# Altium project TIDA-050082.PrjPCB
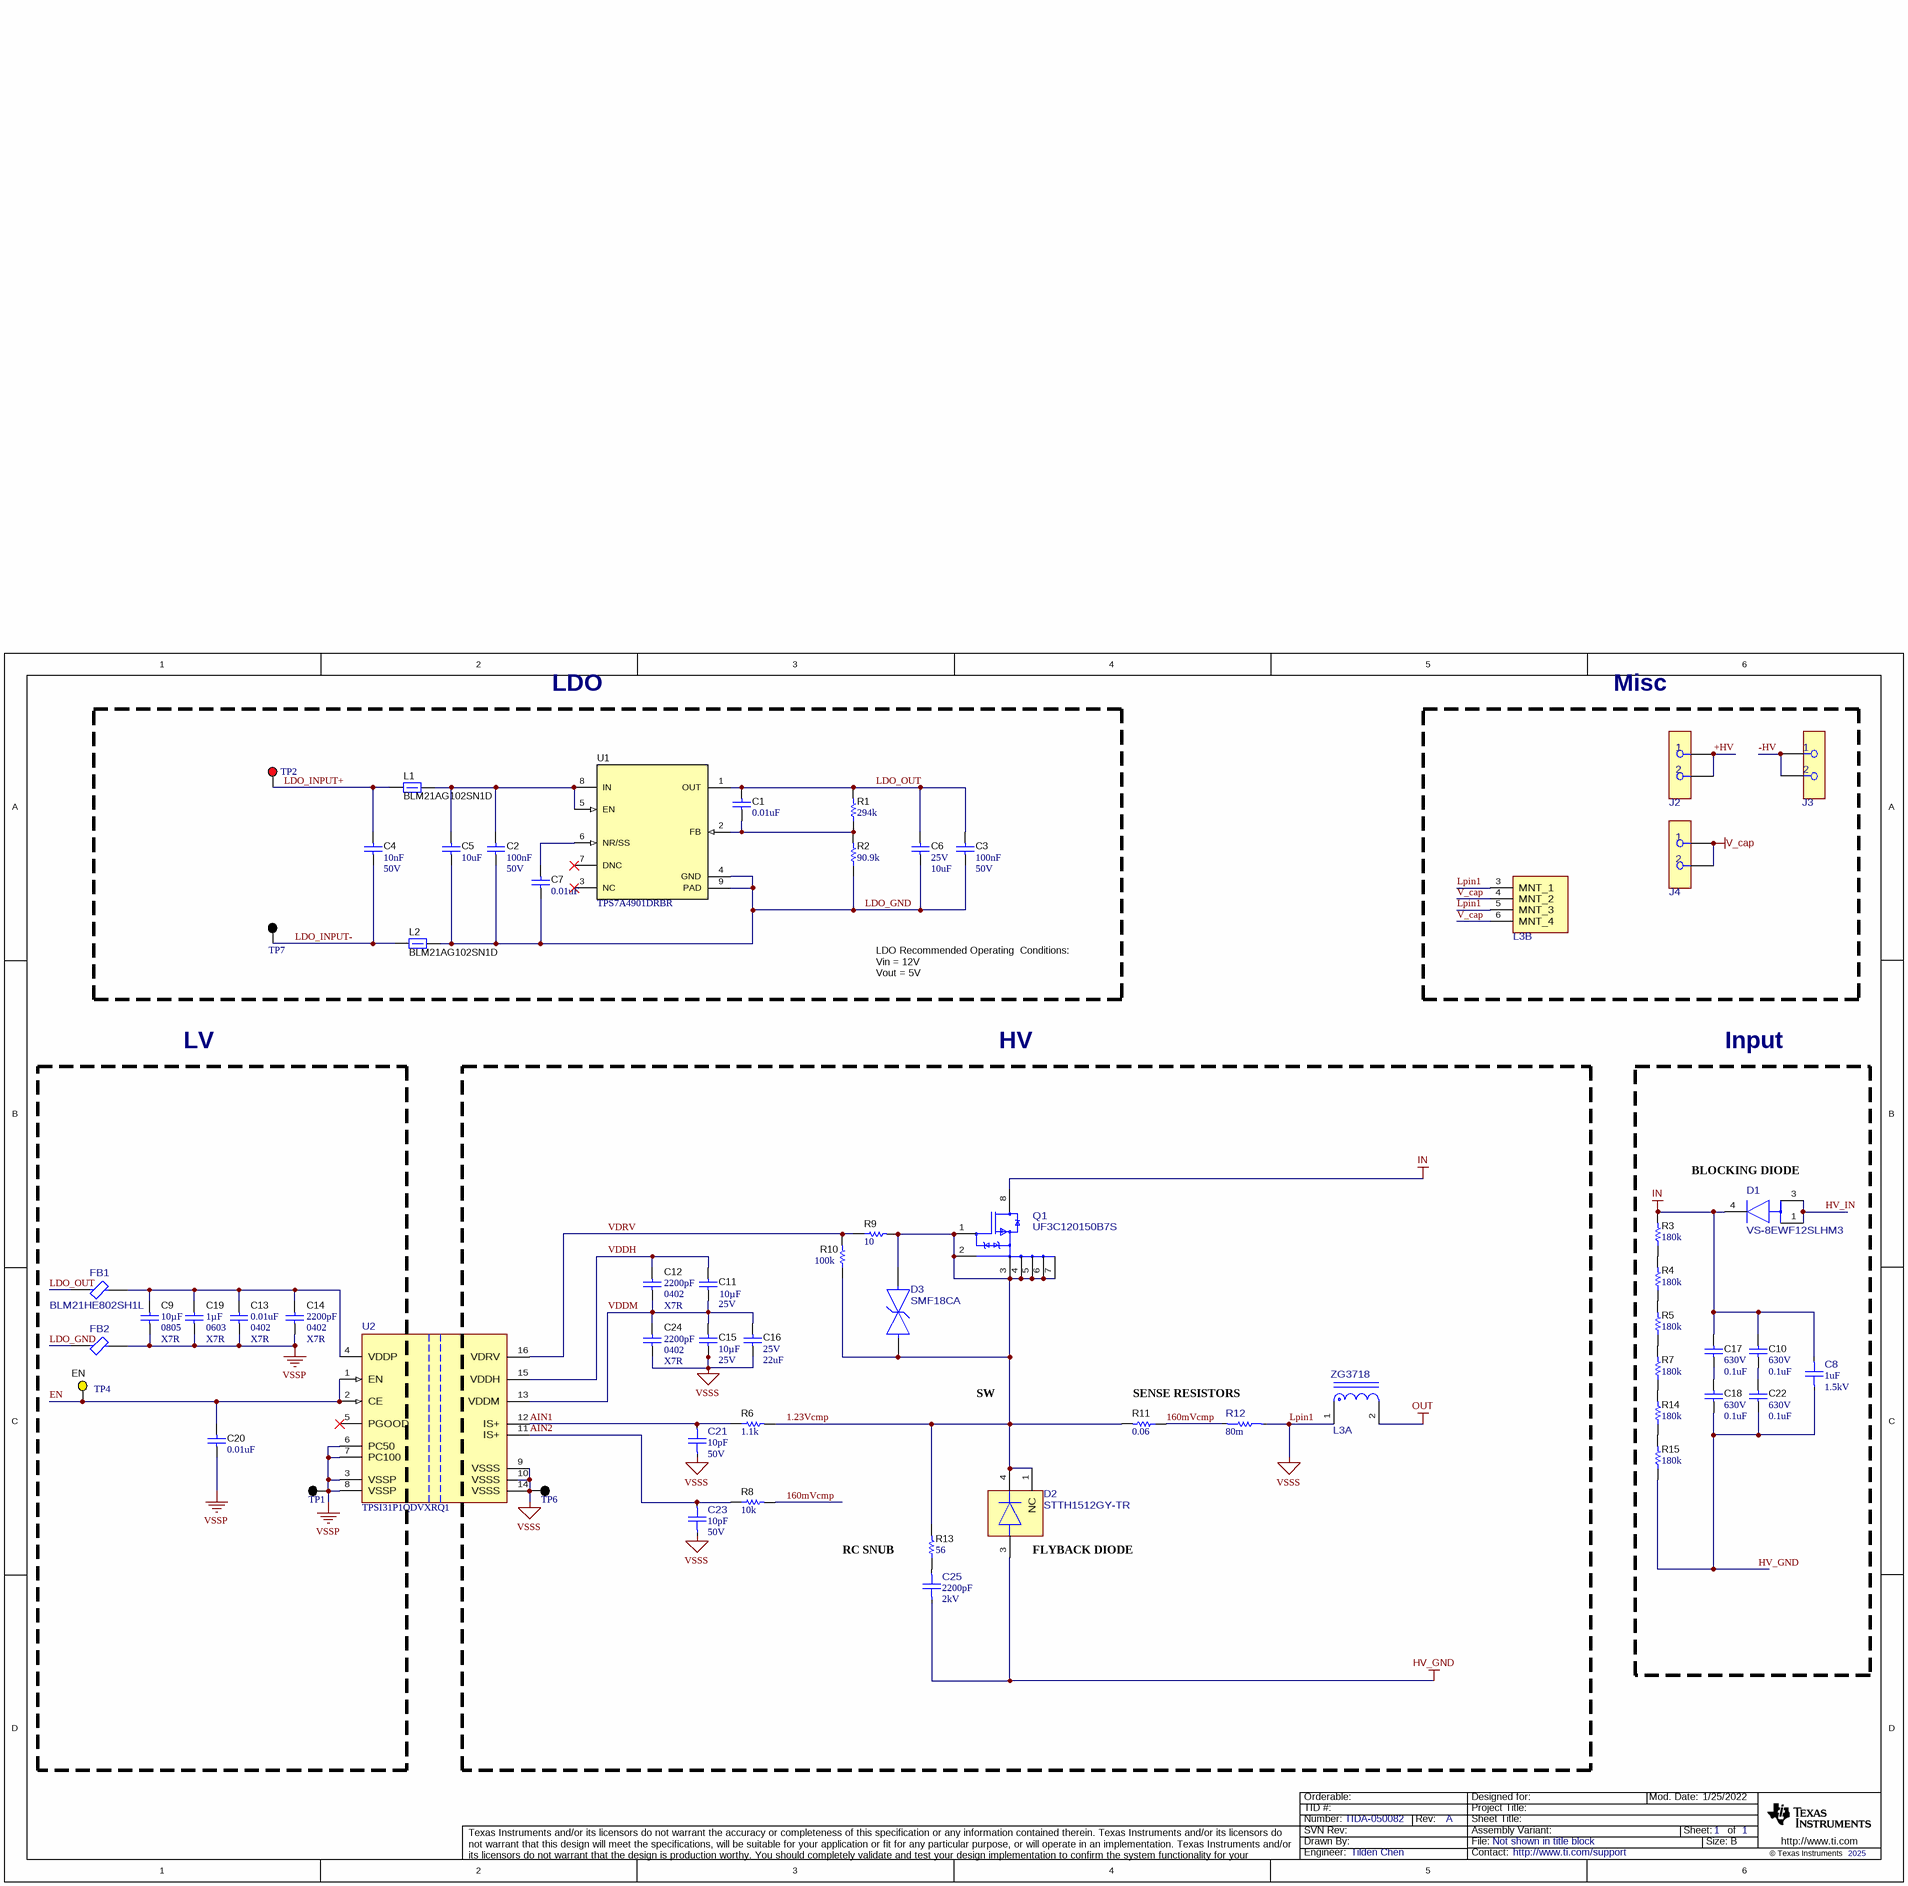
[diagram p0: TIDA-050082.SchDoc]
CopyrightYear: 2025; PCB_Rev: A; PRJ_Engineer: Tilden Chen; PRJ_Number: TIDA-050082; SCH_Rev: A; TechSupport: http://www.ti.com/support
2 sheets, 66 parts. Net scope: global (net labels, ports and power ports of the same name join across sheets).
Board file: TIDA-050082.PcbDoc
Sheets:
  TIDA-050082.SchDoc
  TIDA-050082-Hardware.SchDoc

## Sheet TIDA-050082.SchDoc
size 431 x 279 mm; Date: Not shown in title block; ApprovedBy: Not shown in title block; CheckedBy: Not shown in title block; Author: Not shown in title block; CompanyName: Not shown in title block; Engineer: Not shown in title block; Organization: Not shown in title block; Address1: Not shown in title block; Address2: Not shown in title block; Address3: Not shown in title block; Address4: Not shown in title block; DocumentNumber: 1; Revision: Use project parameter SCH_Rev; SheetNumber: 1; SheetTotal: 1; PageSetup: Record=PageOptions¦CenterHorizontal=True¦CenterVertical=True¦PrintScale=1.00¦XCorrection=1.00¦YCorrection=1.00¦PrintKind=0¦BorderSize=5000000¦LeftOffset=0¦BottomOffset=0¦Orientation=2¦PaperLength=1000¦PaperWidth=1000¦Scale=100¦PaperSource=15¦PrintQuality=600¦MediaType=1¦DitherType=10¦PaperKind=Letter¦PrintScaleMode=1

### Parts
C1  ValueDisplayed: 0.01uF  [0402]  (hidden comment: GRM155R71E103KA01D)
C2  Cap_F: 100nF  VDC_V: 50V  [0603]  (hidden comment: CGA3E2X7R1H104K080AA)
C3  Cap_F: 100nF  VDC_V: 50V  [0603]  (hidden comment: CGA3E2X7R1H104K080AA)
C4  Cap_F: 10nF  VDC_V: 50V  [0603]  (hidden comment: GCM188R71H103KA37D)
C5  ValueDisplayed: 10uF  [0603]  (hidden comment: GRT188R61E106ME13D)
C6  VDC_V: 25V  ValueDisplayed: 10uF  [1206_180]  (hidden comment: GRM31CR71E106KA12L)
C7  ValueDisplayed: 0.01uF  [0402]  (hidden comment: GRM155R71E103KA01D)
C8  ValueDisplayed: 1uF  VDC_V: 1.5kV  [FP-C4AQSBU4100A1WJ_RADIAL-MFG]  (hidden comment: C4AQSBU4100A1WJ)
C9  TempCo: X7R  Cap_Case: 0805  Cap_F: 10µF  [0805_HV]  (hidden comment: GRM21BZ71E106KE15L)
C10  VDC_V: 630V  ValueDisplayed: 0.1uF  [1210_280]  (hidden comment: C1210C104KBRAC7800)
C11  Cap_F: 10µF  VDC_V: 25V  [0805_HV]  (hidden comment: GRM21BZ71E106KE15L)
C12  TempCo: X7R  ValueDisplayed: 2200pF  [0402]  (hidden comment: 885012205027)
C13  TempCo: X7R  ValueDisplayed: 0.01uF  [0402]  (hidden comment: GRM155R71E103KA01D)
C14  TempCo: X7R  ValueDisplayed: 2200pF  [0402]  (hidden comment: 885012205027)
C15  Cap_F: 10µF  VDC_V: 25V  [0805_HV]  (hidden comment: GRM21BZ71E106KE15L)
C16  VDC_V: 25V  ValueDisplayed: 22uF  [0805_HV]  (hidden comment: GRM21BR61E226ME44L)
C17  VDC_V: 630V  ValueDisplayed: 0.1uF  [1210_280]  (hidden comment: C1210C104KBRAC7800)
C18  VDC_V: 630V  ValueDisplayed: 0.1uF  [1210_280]  (hidden comment: C1210C104KBRAC7800)
C19  TempCo: X7R  Cap_F: 1µF  [0603]  (hidden comment: CGA3E1X7R1C105K080AC)
C20  ValueDisplayed: 0.01uF  [0402]  (hidden comment: GRM155R71E103KA01D)
C21  ValueDisplayed: 10pF  VDC_V: 50V  [FP-C0402C100K5RAC7867_0402-MFG]  (hidden comment: C0402C100K5RAC7867)
C22  VDC_V: 630V  ValueDisplayed: 0.1uF  [1210_280]  (hidden comment: C1210C104KBRAC7800)
C23  ValueDisplayed: 10pF  VDC_V: 50V  [FP-C0402C100K5RAC7867_0402-MFG]  (hidden comment: C0402C100K5RAC7867)
C24  TempCo: X7R  ValueDisplayed: 2200pF  [0402]  (hidden comment: 885012205027)
C25  ValueDisplayed: 2200pF  VDC_V: 2kV  [FP-C1206X222KGRACAUTO_1206-MFG]  (hidden comment: C1206X222KGRACAUTO)
D1  VS-8EWF12SLHM3  [FP-VS-8EWF12SLHM3_DPAK-MFG]
D2  STTH1512GY-TR  [FP-STTH1512GY-TR_D2PAK-MFG]
D3  SMF18CA  [FP-SMF18CA_SOD-123FL-MFG]
FB1  BLM21HE802SH1L  [FP-BLM21HE802SH1L_0805-MFG]
FB2  BLM21HE802SH1L  [FP-BLM21HE802SH1L_0805-MFG]  (value not drawn)
J2  691250610002  [FP-691250610002_CONN_TERM_BLOCK2-MFG]  (value not drawn)
J3  691250610002  [FP-691250610002_CONN_TERM_BLOCK2-MFG]  (value not drawn)
J4  691250610002  [FP-691250610002_CONN_TERM_BLOCK2-MFG]  (value not drawn)
L1  BLM21AG102SN1D  [0805_HV]
L2  BLM21AG102SN1D  [0805_HV]
L3  ZG3718  [FP-ZG3718_PTH6-MFG]  (parts A,B of 2)
Q1  UF3C120150B7S  [FP-UF3C120150B7S_D2PAK7-MFG]
R1  ValueDisplayed: 294k  [0402]  (hidden comment: ERJ-2RKF2943X)
R2  ValueDisplayed: 90.9k  [0402]  (hidden comment: ERJ-2RKF9092X)
R3  ValueDisplayed: 180k  [1206]  (hidden comment: CRCW1206180KJNEA)
R4  ValueDisplayed: 180k  [1206]  (hidden comment: CRCW1206180KJNEA)
R5  ValueDisplayed: 180k  [1206]  (hidden comment: CRCW1206180KJNEA)
R6  ValueDisplayed: 1.1k  [0402]  (hidden comment: CRCW04021K10JNED)
R7  ValueDisplayed: 180k  [1206]  (hidden comment: CRCW1206180KJNEA)
R8  ValueDisplayed: 10k  [0402]  (hidden comment: ERJ-2GEJ103X)
R9  ValueDisplayed: 10  [0603]  (hidden comment: CRCW060310R0JNEA)
R10  ValueDisplayed: 100k  [0603]  (hidden comment: ERJ-3GEYJ104V)
R11  ValueDisplayed: 0.06  [2512]  (hidden comment: WSL2512R0600FEA)
R12  value 80m  [FP-TLRP3A20CR080FTE_2512-MFG]  (hidden comment: TLRP3A20CR080FTE)
R13  ValueDisplayed: 56  [1206]  (hidden comment: CRCW120656R0JNEA)
R14  ValueDisplayed: 180k  [1206]  (hidden comment: CRCW1206180KJNEA)
R15  ValueDisplayed: 180k  [1206]  (hidden comment: CRCW1206180KJNEA)
TP1  5011  [Keystone5011]  (value not drawn)
TP2  (no value)  [Keystone5010]
TP4  EN  [Keystone5014]
TP6  5011  [Keystone5011]  (value not drawn)
TP7  5011  [Keystone5011]  (value not drawn)
U1  TPS7A4901DRBR  [DRB0008A]
U2  TPSI31P1QDVXRQ1  [DVX0016A-MFG]

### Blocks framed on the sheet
LDO: C1-C7 L1 L2 R1 R2 TP2 TP7 U1
Misc: J2-J4 L3
LV: C9 C13 C14 C19 C20 FB1 FB2 TP1 TP4
HV: C11 C12 C15 C16 C21 C23-C25 D2 D3 L3 Q1 R6 R8-R13 TP6
Input: C8 C10 C17 C18 C22 D1 R3-R5 R7 R14 R15

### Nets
HV_GND: C8.1 C18.2 C22.2 C25.1 D2.3(A) R15.1
IN: C8.2 C10.1 C17.1 D1.4(Cathode) Q1.8(D) R3.2
Lpin1: C15.2 C16.2 C21.1 C23.1 C24.2 L3.1 L3.3(MNT_1) L3.5(MNT_3) R12.1 TP6.1 U2.9(VSSS) U2.10(VSSS) U2.14(VSSS)  [also labelled VSSS]
OUT: L3.2
V_cap: J4.1 J4.2 L3.4(MNT_2) L3.6(MNT_4)
VSSP: C9.2 C13.2 C14.2 C19.2 C20.2 FB2.2 TP1.1 U2.3(VSSP) U2.6(PC50) U2.7(PC100) U2.8(VSSP)
1.23Vcmp: D2.1(NC) D2.4(K) D3.1 D3.2 Q1.1(G) Q1.2(KS) Q1.3(S) Q1.4(S) Q1.5(S) Q1.6(S) Q1.7(S) R6.2 R9.2 R10.1 R11.2 R13.2
160mVcmp: R8.2 R11.1 R12.2
+HV: J2.1 J2.2
-HV: J3.1 J3.2
AIN1: C21.2 R6.1 U2.12(IS+)
AIN2: C23.2 R8.1 U2.11(IS+)
EN: C20.1 TP4.1 U2.1(EN) U2.2(CE)
HV_IN: D1.1(Anode) D1.3(Anode)
LDO_GND: C2.2 C3.2 C5.2 C6.2 C7.2 FB2.1 L2.2 R2.1 U1.4(GND) U1.9(PAD)
LDO_INPUT+: C4.1 L1.1 TP2.1
LDO_INPUT-: C4.2 L2.1 TP7.1
LDO_OUT: C1.1 C3.1 C6.1 FB1.1 R1.2 U1.1(OUT)
VDDH: C11.1 C12.1 U2.15(VDDH)
VDDM: C11.2 C12.2 C15.1 C16.1 C24.1 U2.13(VDDM)
VDRV: R9.1 R10.2 U2.16(VDRV)
NetC1_2: C1.2 R1.1 R2.2 U1.2(FB)
NetC2_1: C2.1 C5.1 L1.2 U1.5(EN) U1.8(IN)
NetC7_1: C7.1 U1.6(NR/SS)
NetC9_1: C9.1 C13.1 C14.1 C19.1 FB1.2 U2.4(VDDP)
NetC10_2: C10.2 C22.1
NetC17_2: C17.2 C18.1
NetC25_2: C25.2 R13.1
NetR3_1: R3.1 R4.2
NetR4_1: R4.1 R5.2
NetR5_1: R5.1 R7.2
NetR7_1: R7.1 R14.2
NetR14_1: R14.1 R15.2

Not connected (* = marked no-connect by the designer): U1 3(NC)* 7(DNC)*; U2 5(PGOOD)*

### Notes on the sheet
- LDO Recommended Operating  Conditions:
  Vin = 12V
  Vout = 5V
- (near D1) BLOCKING DIODE
- SW
- SENSE RESISTORS
- RC SNUB
- (near D2) FLYBACK DIODE

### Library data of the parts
C1 C7 C13 C20 = CMP-0006658-2: CAP, CERM, 0.01 uF, 25 V, +/- 10%, X7R, 0402; Manufacturer: MuRata; TaMin_C: -55°C; Polarized: N; SizeAreaWB_mm2: 3; Value1: Unknown; U/M: EA; Value: 0.01uF; TaMax_C: 125°C; SizeZ_mm: 0.6; SizeX_mm: 1; SizeY_mm: 0.5; Value2: 25V; Cap_F: 10nF; AEC Category: Q200
C2 C3 = CMP-0007078-4: CAP, CERM, 0.1 uF, 50 V, +/- 10%, X7R, AEC-Q200 Grade 1, 0603; Manufacturer: TDK; TaMin_C: -55°C; ESR_ohm: 29.6m; Polarized: N; SizeAreaWB_mm2: 4.68; Value1: 0.0296 ohm; U/M: EA; Value: 0.1uF; TaMax_C: 125°C; SizeZ_mm: 1; SizeX_mm: 1.6; SizeY_mm: 0.8; SizeArea_mm2: 1.28; AEC Qualified: Y; IRMS_A: 971.99mA; AEC Category: Q200
C4 = CMP-0007143-4: CAP, CERM, 0.01 uF, 50 V, +/- 10%, X7R, AEC-Q200 Grade 1, 0603; Manufacturer: MuRata; TaMin_C: -55°C; Polarized: N; SizeAreaWB_mm2: 4.68; Value1: Unknown; U/M: EA; Value: 0.01uF; TaMax_C: 125°C; SizeZ_mm: 1; SizeX_mm: 1.6; SizeY_mm: 0.8; SizeArea_mm2: 1.28; AEC Qualified: Y; AEC Category: Q200
C5 = CMP-0007501-5: CAP, CERM, 10 uF, 25 V, +/- 20%, X5R, 0603; Manufacturer: MuRata; TaMin_C: -55°C; Polarized: N; SizeAreaWB_mm2: 4.68; Value1: Unknown; U/M: EA; Value: 10uF; TaMax_C: 85°C; SizeZ_mm: 1; SizeX_mm: 1.6; SizeY_mm: 0.8; Value2: 25V; SizeArea_mm2: 1.28; Cap_F: 10µF; AEC Category: Q200
C6 = CMP-0008965-2: CAP, CERM, 10 uF, 25 V, +/- 10%, X7R, 1206; Manufacturer: MuRata; TaMin_C: -55°C; Polarized: N; SizeAreaWB_mm2: 10.92; Value1: Unknown; U/M: EA; Value: 10uF; TaMax_C: 125°C; SizeZ_mm: 1.8; SizeX_mm: 3.2; SizeY_mm: 1.6; Cap_Case: 2220; SizeArea_mm2: 5.12; Cap_F: 10µF; AEC Category: Q200
C8 = CMP-0122633-1: 1 µF Film Capacitor 1500V (1.5kV) Polypropylene (PP), Metallized Radial; Manufacturer: KEMET; AEC Grade: Grade 2; AEC Qualified: Yes; Cap_F: 1µF; SizeZ_mm: 20.2mm; Tolerance_%: 5%; Value: 1µF
C9 = CMP-0008378-2: CAP, CERM, 10 uF, 25 V, +/- 10%, X7R, 0805; Manufacturer: MuRata; TaMin_C: -55°C; Polarized: N; SizeAreaWB_mm2: 6.75; Value1: Unknown; U/M: EA; Value: 10uF; TaMax_C: 125°C; SizeZ_mm: 1.45; SizeX_mm: 2; SizeY_mm: 1.25; Value2: 25V; SizeArea_mm2: 2.5; AEC Category: Q200
C10 C17 C18 C22 = CMP-0009076-1: CAP, CERM, 0.1 uF, 630 V, +/- 10%, X7R, 1210; Manufacturer: Kemet; TaMin_C: -55°C; Polarized: N; SizeAreaWB_mm2: 14.7; Value1: Unknown; U/M: EA; Value: 0.1uF; TaMax_C: 125°C; SizeZ_mm: 2.8; SizeX_mm: 3.2; SizeY_mm: 2.5; Cap_Case: 1210; SizeArea_mm2: 8; Cap_F: 100nF; AEC Category: Q200
C11 C15 = CMP-0008378-2: CAP, CERM, 10 uF, 25 V, +/- 10%, X7R, 0805; Manufacturer: MuRata; TaMin_C: -55°C; Polarized: N; SizeAreaWB_mm2: 6.75; Value1: Unknown; U/M: EA; Value: 10uF; TaMax_C: 125°C; SizeZ_mm: 1.45; SizeX_mm: 2; SizeY_mm: 1.25; Cap_Case: 0805; SizeArea_mm2: 2.5; AEC Category: Q200
C12 C14 C24 = CMP-0006225-2: CAP, CERM, 2200 pF, 16 V, +/- 10%, X7R, 0402; Manufacturer: Wurth Elektronik; TaMin_C: -55°C; Polarized: N; SizeAreaWB_mm2: 3; Value1: Unknown; U/M: EA; Value: 2200pF; TaMax_C: 125°C; SizeZ_mm: 0.6; SizeX_mm: 1; SizeY_mm: 0.5; Value2: 16V; Cap_F: 2.2nF; AEC Category: Q200
C16 = CMP-0008305-2: CAP, CERM, 22 uF, 25 V, +/- 20%, X5R, 0805; Manufacturer: MuRata; TaMin_C: -55°C; Polarized: N; SizeAreaWB_mm2: 6.75; Value1: Unknown; U/M: EA; Value: 22uF; TaMax_C: 85°C; SizeZ_mm: 1.45; SizeX_mm: 2; SizeY_mm: 1.25; Cap_Case: 0805; SizeArea_mm2: 2.5; Cap_F: 22µF; AEC Category: Q200
C19 = CMP-0079607-1: CAP, CERM, 1 µF, 16 V,+/- 10%, X7R, AEC-Q200 Grade 1, 0603; Manufacturer: TDK; TaMin_C: -55°C; Polarized: N; SizeAreaWB_mm2: 4.68; U/M: EA; Value: 1uF; TaMax_C: 125°C; SizeZ_mm: 1; SizeX_mm: 1.6; SizeY_mm: 0.8; Value2: 16V; SizeArea_mm2: 1.28; AEC Qualified: Y; AEC Category: Q200
C21 C23 = CMP-0122034-1: 10 pF ±10% 50V Ceramic Capacitor X7R 0402 (1005 Metric); Manufacturer: KEMET; AEC Qualified: No; SizeZ_mm: 0.55mm; TempCo: 15%; Value: 10pF
C25 = CMP-0124208-1: 2200 pF ±10% 2000V (2kV) Ceramic Capacitor X7R 1206 (3216 Metric); Manufacturer: KEMET; AEC Grade: Grade 1; AEC Qualified: Yes; Cap_F: 2.2nF; SizeZ_mm: 1.85mm; TempCo: 15%; Value: 2.2nF
D1 = CMP-0127376-1: Diode 1200 V 8A Surface Mount TO-252AA (DPAK); Manufacturer: Vishay; AEC Qualified: No; SizeZ_mm: 2.52mm; TJmax_C: 150°C; Vf_V: 1.2kV; Max Surge Forward Current: 150A; Peak Reverse Current: 0.1mA
D2 = CMP-0123451-1: Rectifier Diode Switching 1.2KV 15A 75ns Automotive 3-Pin(2+Tab) D2PAK T/R; Manufacturer: STMicroelectronics; AEC Qualified: Yes; SizeZ_mm: 4.85mm; TJmax_C: 175°C; AEC Grade: Grade 0; Max Surge Forward Current: 200A; Peak Reverse Current: 15uA; Standoff Height: 0mm
D3 = CMP-0127967-1: Diode TVS Single Bi-Dir 18V 200W 2-Pin SOD-123FL T/R; Manufacturer: Littelfuse; AEC Qualified: No; SizeZ_mm: 1.1mm; Ipp: 6.8A; Breakdown Voltage: 20V; Clamping Voltage: 29.2V; Direction: Bidirectional; Number Of Channels: 1; Standoff Height: 0mm; TJmax_C: +150°C
FB1 FB2 = CMP-0126464-1: 8 kOhms @ 100 MHz 1 Signal Line Ferrite Bead 0805 (2012 Metric) 650mA 700mOhm; Manufacturer: Murata; DCR_ohm: 0.7; SizeZ_mm: 1.45mm; AEC Grade: Grade 1; AEC Qualified: Yes; Impedance At Frequency: 8000Ω @ 100MHz; Test Frequency: 100MHz; Tolerance_%: 25%
J2-J4 = CMP-0093233-2: 2 Position Wire to Board Terminal Block Horizontal with Board 0.250" (6.35mm) Through Hole; Manufacturer: Wurth Electronics; SizeZ_mm: 21.6mm; Min Wire Gauge: 30; Is Female: yes; Row_Count: 1; Voltage_V: 450V; AEC Qualified: No; Max Wire Gauge: 10; Conn Gender: Female; Current_A: 32A; ContactFinish: Zinc
L1 L2 = CMP-0003356-1: Ferrite Bead, 1000 ohm @ 100 MHz, 0.5 A, 0805; Manufacturer: MuRata; ZTyp@100MHz_Ohm: 1k; SizeAreaWB_mm2: 6.75; DCR_ohm: 0.28; Value1: 0.28 ohm; Imax_A: 500mA; SizeZ_mm: 1.45; SizeX_mm: 2; SizeY_mm: 1.25; Value2: 0.5A; SizeArea_mm2: 2.5
L3 = CMP-0127410-1: Power inductor, 100uH-9.6A, Flat wire, TH, PQ26; Manufacturer: Coilcraft; AEC Qualified: No; DCR_ohm: 25m; Ind_H: 100µH; SizeZ_mm: 21.5mm; Value: 100uH; Test Frequency: 100kHz; Tolerance_%: 10%
Q1 = CMP-0096955-1: N-Channel 1200 V 17A (Tc) 136W (Tc) Surface Mount D2PAK-7; Manufacturer: UnitedSiC; Turn On Delay Time: 32ns; Typ Forward Diode Voltage: 1.46V; Pulse Drain Current: 38A; Reverse Recovery Time: 24ns; SizeZ_mm: 4.81mm; VdsMax_V: 2V; Reverse Recovery Charge: 67nC; AEC Qualified: No; Number Of Channels: 1; Input Capacitace At Vds: 738pF @ 100V; Standoff Height: 0mm; Threshold Vgs Max: 5.5V; Drain To Source Breakdown Voltage: 1200V; QgTyp_nC: 25.7nC @ 12V; Rdson45_ohm: 0.15; ChMode: False; Threshold Vgs Min: 3.5V; Vgs_V: 25V; TJmax_C: +175°C
R1 = CMP-0026693-1: RES, 294 k, 1%, 0.1 W, AEC-Q200 Grade 0, 0402; Manufacturer: Panasonic; Power_W: 100mW; TempCo: 100 ppm/C; U/M: EA; Value: 294k; EIA_Code: E96; SizeX_mm: 1; SizeY_mm: 0.5; SizeZ_mm: 0.6; Value2: 0.1W; AEC Qualified: Y; VDC_V: 50V; AEC Grade: 0; AEC Category: Q200
R2 = CMP-0026711-1: RES, 90.9 k, 1%, 0.1 W, AEC-Q200 Grade 0, 0402; Manufacturer: Panasonic; Power_W: 100mW; TempCo: 100 ppm/C; Value_Code: 90k9; U/M: EA; Value: 90.9k; EIA_Code: E96; SizeX_mm: 1; SizeY_mm: 0.5; SizeZ_mm: 0.6; Value2: 0.1W; AEC Qualified: Y; VDC_V: 50V; AEC Grade: 0; AEC Category: Q200
R3-R5 R7 R14 R15 = CMP-0018599-3: RES, 180 k, 5%, 0.25 W, AEC-Q200 Grade 0, 1206; Manufacturer: Vishay-Dale; Power_W: 250mW; TempCo: 200 ppm/C; Value: 180k; EIA_Code: E24; SizeX_mm: 3.2; SizeY_mm: 1.6; SizeZ_mm: 1.35; Value2: 0.25W; SizeArea_mm2: 5.12; AEC Qualified: Y; VDC_V: 200V; AEC Category: Q200; AEC Grade: 0
R6 = CMP-0026853-5: RES, 1.1 k, 5%, 0.063 W, AEC-Q200 Grade 0, 0402; Manufacturer: Vishay-Dale; Power_W: 63mW; TempCo: 200 ppm/C; Value_Code: 1k10; Value: 1.1k; EIA_Code: E24; SizeX_mm: 1; SizeY_mm: 0.5; SizeZ_mm: 0.6; Value2: 0.063W; AEC Qualified: Y; VDC_V: 50V; AEC Category: Q200; AEC Grade: 0
R8 = CMP-0026994-4: RES, 10 k, 5%, 0.1 W, AEC-Q200 Grade 0, 0402; Manufacturer: Panasonic; Power_W: 100mW; TempCo: 200 ppm/C; Value_Code: 10k0; U/M: EA; Value: 10k; EIA_Code: E24; SizeX_mm: 1; SizeY_mm: 0.5; SizeZ_mm: 0.6; Value2: 0.1W; AEC Qualified: Y; VDC_V: 50V; AEC Grade: 0; AEC Category: Q200
R9 = CMP-0025703-4: RES, 10, 5%, 0.1 W, AEC-Q200 Grade 0, 0603; Manufacturer: Vishay-Dale; Power_W: 100mW; TempCo: 200 ppm/C; Value_Code: 10R0; Value: 10; EIA_Code: E24; SizeX_mm: 1.6; SizeY_mm: 0.8; SizeZ_mm: 1; Value2: 0.1W; SizeArea_mm2: 1.28; AEC Qualified: Y; VDC_V: 75V; AEC Category: Q200; AEC Grade: 0
R10 = CMP-0025875-3: RES, 100 k, 5%, 0.1 W, AEC-Q200 Grade 0, 0603; Manufacturer: Panasonic; Power_W: 100mW; TempCo: 200 ppm/C; U/M: EA; Value: 100k; EIA_Code: E24; SizeX_mm: 1.6; SizeY_mm: 0.8; SizeZ_mm: 1; Value2: 0.1W; SizeArea_mm2: 1.28; AEC Qualified: Y; VDC_V: 50V; AEC Grade: 0; AEC Category: Q200
R11 = CMP-0015855-2: RES, 0.06, 1%, 1 W, 2512; Manufacturer: Vishay-Dale; Power_W: 1W; TempCo: 75 ppm/C; Value_Code: R060; U/M: EA; Value: 0.06; Res_ohm: 60m; SizeX_mm: 6.3; SizeY_mm: 3.2; SizeZ_mm: 0.71; SizeArea_mm2: 20.16; AEC Category: Q200
R12 = CMP-0126009-1: 80 mOhms ±1% 2W Chip Resistor 2512 (6432 Metric) Anti-Sulfur, Automotive AEC-Q200, Current Sense Metal Element; Manufacturer: TE Connectivity; AEC Grade: Grade 0; AEC Qualified: Yes; SizeZ_mm: 0.9mm; TempCo: 25ppm/°C
R13 = CMP-0018702-3: RES, 56, 5%, 0.25 W, AEC-Q200 Grade 0, 1206; Manufacturer: Vishay-Dale; Power_W: 250mW; TempCo: 200 ppm/C; Value_Code: 56R0; Value: 56; EIA_Code: E24; SizeX_mm: 3.2; SizeY_mm: 1.6; SizeZ_mm: 1.35; Value2: 0.25W; SizeArea_mm2: 5.12; AEC Qualified: Y; VDC_V: 200V; AEC Category: Q200; AEC Grade: 0
TP1 TP6 TP7 = CMP-0055148-2: Test Point, Multipurpose, Black, TH; Manufacturer: Keystone Electronics; CNHeader: FALSE; ContactFinish: Silver; Green_REACh: Passed; Green_Lifecycle: Active; CT: TRUE
TP2 = CMP-0055147-2: Test Point, Multipurpose, Red, TH; Manufacturer: Keystone Electronics; CNHeader: FALSE; Green_Lifecycle: Active; Green_REACh: Passed; ContactFinish: Silver; CT: TRUE
TP4 = CMP-0055151-2: Test Point, Multipurpose, Yellow, TH; Manufacturer: Keystone Electronics; CNHeader: FALSE; Green_Lifecycle: Active; Green_REACh: Passed; ContactFinish: Silver; CT: TRUE
U1 = CMP-0073868-3: Vin 3V to 36V, 150mA, Ultra-Low-Noise, High-PSRR Low-Dropout (LDO) Linear Regulator, DRB0008A (VSON-8); Manufacturer: Texas Instruments; Alternate PartNumber: TPS7A4901DRBT; AEC Category: Q200; CompType: IC; SizeZ_mm: 1.0; Rating: Catalog; SizeAreaWB_mm2: 16.0; SizeX_mm: 3.0; SizeArea_mm2: 9.0; AEC Qualified: N
U2 = CMP-0122535-1: Isolated Automotive Active Pre-charge Controller with Integrated Gate Driver and Bias Supply; Manufacturer: Texas Instruments; SizeZ_mm: 2.6mm; AEC Qualified: Yes; AEC Grade: Grade 1; Max Power Dissipation: 250mW; Max Supply Voltage: 5.5V; Min Supply Voltage: 4.5V; Nominal Supply Current: 5.3-35mA; Number Of Drivers: 1; Output Voltage: 15.8V; Standoff Height: 0.1mm; TaMax_C: +125°C; TaMin_C: -40°C; TJmax_C: +150°C

## Sheet TIDA-050082-Hardware.SchDoc
size 431 x 279 mm; Date: Not shown in title block; ApprovedBy: Not shown in title block; CheckedBy: Not shown in title block; Author: Not shown in title block; CompanyName: Not shown in title block; Engineer: Not shown in title block; Organization: Not shown in title block; Address1: Not shown in title block; Address2: Not shown in title block; Address3: Not shown in title block; Address4: Not shown in title block; DocumentNumber: 1; Revision: Use project parameter SCH_Rev; SheetNumber: 1; SheetTotal: 1; PageSetup: Record=PageOptions¦CenterHorizontal=True¦CenterVertical=True¦PrintScale=1.00¦XCorrection=1.00¦YCorrection=1.00¦PrintKind=0¦BorderSize=5000000¦LeftOffset=0¦BottomOffset=0¦Orientation=2¦PaperLength=1000¦PaperWidth=1000¦Scale=100¦PaperSource=15¦PrintQuality=600¦MediaType=1¦DitherType=10¦PaperKind=Letter¦PrintScaleMode=1
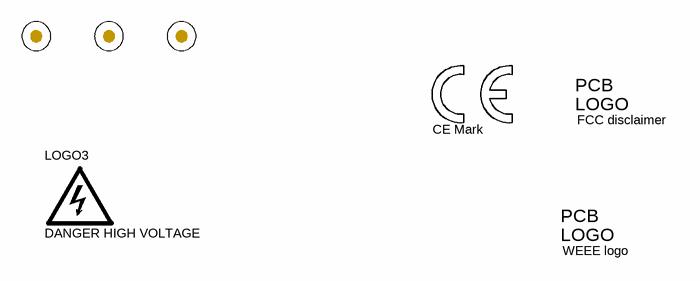
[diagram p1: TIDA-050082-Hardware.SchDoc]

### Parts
FID1  Fiducial  [Fiducial10-20]  (value not drawn)
FID2  Fiducial  [Fiducial10-20]  (value not drawn)
FID3  Fiducial  [Fiducial10-20]  (value not drawn)
Logo1  CE Mark  [CE_Mark_5mm]  (no BOM)
Logo2  FCC disclaimer  [FCC_disclaimer]  (no BOM)
LOGO3  DANGER HIGH VOLTAGE  [IEC_HighVoltage_Small]  (no BOM)
Logo4  WEEE logo  [WEEE_Minimum]  (no BOM)

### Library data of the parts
FID1-FID3 = CMP-0077181-1: Fiducial mark.  There is nothing to buy or mount.
Logo1 = CMP-0074844-1: SymbolCreator: a0412235
Logo2 = CMP-0074847-1: FCC_disclaimer; Library Reference: Logo
LOGO3 = CMP-0074835-1: IEC 61010-1 High Voltage Warning; SymbolCreator: a0412235
Logo4 = CMP-0074769-1

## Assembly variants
001: all parts fitted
